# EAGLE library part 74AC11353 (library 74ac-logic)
Dual 4 to 1 line DATA SELECTOR/MULTIPLEXER
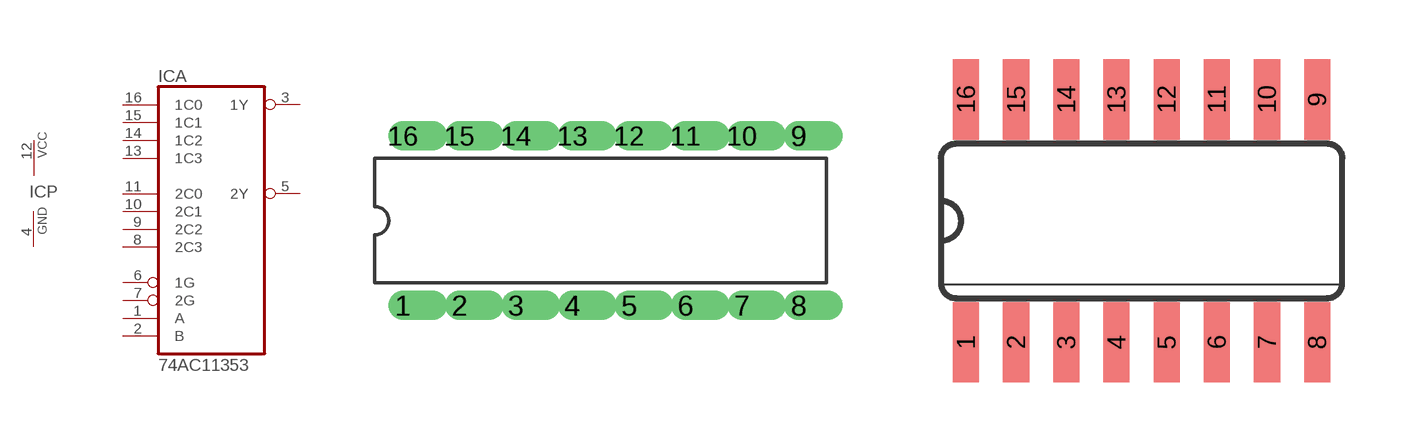
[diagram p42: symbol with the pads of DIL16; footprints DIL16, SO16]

Designator prefix IC; gates A=7411353 P=PWRN

## 74AC11353  [DIL16]
1  A:A  in
2  A:B  in
3  A:1Y  hiz
4  P:GND  pwr
5  A:2Y  hiz
6  A:1G  in
7  A:2G  in
8  A:2C3  in
9  A:2C2  in
10  A:2C1  in
11  A:2C0  in
12  P:VCC  pwr
13  A:1C3  in
14  A:1C2  in
15  A:1C1  in
16  A:1C0  in

## 74AC11353D  [SO16]
Pads as for DIL16

## Footprint DIL16 (pad centres in mm)
Dual In Line
drill 0.813 offset: 1 -8.89,-3.81; 2 -6.35,-3.81; 3 -3.81,-3.81; 4 -1.27,-3.81; 5 1.27,-3.81; 6 3.81,-3.81; 7 6.35,-3.81; 8 8.89,-3.81; 9 8.89,3.81; 10 6.35,3.81; 11 3.81,3.81; 12 1.27,3.81; 13 -1.27,3.81; 14 -3.81,3.81; 15 -6.35,3.81; 16 -8.89,3.81

## Footprint SO16 (pad centres in mm)
Small Outline package 150 mil
smd 0.66 x 2.032: 1 -4.445,-3.073; 2 -3.175,-3.073; 3 -1.905,-3.073; 4 -0.635,-3.073; 5 0.635,-3.073; 6 1.905,-3.073; 7 3.175,-3.073; 8 4.445,-3.073; 9 4.445,3.073; 10 3.175,3.073; 11 1.905,3.073; 12 0.635,3.073; 13 -0.635,3.073; 14 -1.905,3.073; 15 -3.175,3.073; 16 -4.445,3.073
